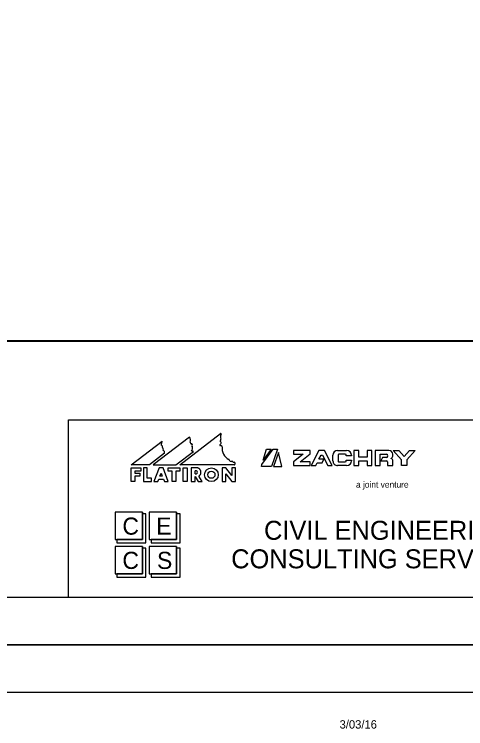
# Model space of a CAD drawing. Extents: x -2251 to 10196, y -13470 to 1199.
# Drawn here: x 1285.2 to 1522.9, y -13469.8 to -13093.7 of the extents above; entities that cross this region are included whole.
import ezdxf

# ---------------------------------------------------------------- set-up
doc = ezdxf.new("R2010")
doc.units = 0
for name, color, linetype in [('Level 3', 7, 'Continuous'), ('RD_SHT_Bndy', 7, 'Continuous'), ('RD_SHT_Iplotshp', 7, 'Continuous'), ('RD_SHT_Logo', 7, 'Continuous'), ('RD_SHT_Misc1', 7, 'Continuous'), ('RD_SHT_Snap', 7, 'Continuous'), ('RD_SHT_TX', 7, 'Continuous'), ('RD_TX_RoadID', 7, 'Continuous')]:
    doc.layers.add(name, color=color, linetype=linetype)

msp = doc.modelspace()

# ---------------------------------------------------------------- linework, layer by layer
at = {"layer": 'Level 3'}
msp.add_line((1465.07, -13363.99), (1465.07, -13363.99), dxfattribs=at)
msp.add_line((1465.07, -13363.99), (1465.07, -13363.99), dxfattribs=at)
msp.add_line((1465.07, -13363.99), (1465.07, -13363.99), dxfattribs=at)
msp.add_line((1465.07, -13363.99), (1465.07, -13363.99), dxfattribs=at)
at = {"layer": 'RD_SHT_Bndy'}
for p, q in [((103.1, -13400.65), (1778.1, -13400.65)), ((1791.65, -13425.65), (31.65, -13425.65)), ((1791.6, -13450.7), (31.6, -13450.65))]:
    msp.add_line(p, q, dxfattribs=at)
msp.add_lwpolyline([(153.4, -12401.26), (1731.08, -12401.26), (1731.08, -13265.57), (153.4, -13265.57)], close=True, dxfattribs=at)
at = {"layer": 'RD_SHT_Iplotshp'}
msp.add_lwpolyline([(-3.35, -12325.65), (1796.65, -12325.65), (1796.65, -13425.65), (-3.35, -13425.65)], close=True, dxfattribs=at)
at = {"layer": 'RD_SHT_Logo'}
for p, q in [((1377.35, -13316.27), (1358.31, -13330.86)), ((1372.32, -13330.86), (1393.74, -13314.44)), ((1346.7, -13330.86), (1362.98, -13318.38)), ((1370.3, -13330.86), (1379.48, -13323.82)), ((1415.56, -13330.77), (1421.47, -13322.59)), ((1420.48, -13322.59), (1416.24, -13328.47)), ((1416.24, -13328.47), (1417.96, -13322.59)), ((1417.96, -13322.59), (1420.48, -13322.59)), ((1423.82, -13322.59), (1420.68, -13331.76)), ((1421.47, -13322.59), (1423.82, -13322.59)), ((1440.93, -13323.35), (1432.22, -13323.35)), ((1432.22, -13323.35), (1432.22, -13325.3)), ((1440.93, -13325.16), (1440.93, -13323.35)), ((1445.58, -13323.35), (1441.53, -13331.3)), ((1448.58, -13323.35), (1445.58, -13323.35)), ((1452.63, -13331.3), (1448.58, -13323.35)), ((1455.44, -13323.35), (1460.18, -13323.35)), ((1466.62, -13323.35), (1464.02, -13323.35)), ((1464.02, -13323.35), (1464.02, -13331.3)), ((1466.62, -13326.8), (1466.62, -13323.35)), ((1470.9, -13323.35), (1470.9, -13326.8)), ((1473.51, -13323.35), (1470.9, -13323.35)), ((1473.5, -13331.3), (1473.51, -13323.35)), ((1482.43, -13323.35), (1475.13, -13323.35)), ((1475.13, -13323.35), (1475.13, -13331.3)), ((1484.68, -13323.35), (1487.64, -13323.35)), ((1489.08, -13328.24), (1484.68, -13323.35)), ((1487.64, -13323.35), (1490.48, -13326.51)), ((1490.48, -13326.51), (1493.32, -13323.35)), ((1496.28, -13323.35), (1491.88, -13328.24)), ((1493.32, -13323.35), (1496.28, -13323.35)), ((1364.27, -13324.74), (1356.29, -13330.86)), ((1424.24, -13324.44), (1421.74, -13331.76)), ((1425.99, -13331.76), (1424.24, -13324.44)), ((1437.2, -13325.3), (1432.22, -13329.24)), ((1432.22, -13325.3), (1437.2, -13325.3)), ((1435.63, -13329.35), (1440.93, -13325.16)), ((1445.57, -13327.99), (1446.71, -13325.75)), ((1446.71, -13325.75), (1447.44, -13325.75)), ((1447.44, -13325.75), (1450.27, -13331.3)), ((1452.94, -13328.8), (1452.94, -13325.85)), ((1455.64, -13325.8), (1455.64, -13328.85)), ((1459.48, -13325.3), (1456.14, -13325.3)), ((1459.98, -13326.15), (1459.98, -13325.8)), ((1462.68, -13326.15), (1459.98, -13326.15)), ((1462.68, -13325.85), (1462.68, -13326.15)), ((1470.9, -13326.8), (1466.62, -13326.8)), ((1477.83, -13331.3), (1477.83, -13325.31)), ((1477.83, -13325.31), (1481.07, -13325.31)), ((1479.03, -13326.97), (1478.11, -13328.77)), ((1481.07, -13326.97), (1479.03, -13326.97)), ((1483.68, -13327.6), (1483.68, -13327.47)), ((1484.43, -13326.36), (1484.43, -13325.35)), ((1356.29, -13330.86), (1346.7, -13330.86)), ((1358.31, -13330.86), (1370.3, -13330.86)), ((1401.19, -13330.86), (1372.32, -13330.86)), ((1415.27, -13331.76), (1415.56, -13330.77)), ((1432.22, -13329.24), (1432.22, -13331.3)), ((1432.22, -13331.3), (1440.93, -13331.3)), ((1440.93, -13329.35), (1435.63, -13329.35)), ((1440.93, -13331.3), (1440.93, -13329.35)), ((1441.53, -13331.3), (1443.88, -13331.3)), ((1443.88, -13331.3), (1444.65, -13329.79)), ((1444.65, -13329.79), (1447.23, -13329.79)), ((1448.15, -13327.99), (1445.57, -13327.99)), ((1447.23, -13329.79), (1448.15, -13327.99)), ((1450.27, -13331.3), (1452.63, -13331.3)), ((1460.18, -13331.3), (1455.44, -13331.3)), ((1456.14, -13329.35), (1459.48, -13329.35)), ((1459.98, -13328.5), (1462.68, -13328.5)), ((1459.98, -13328.85), (1459.98, -13328.5)), ((1462.68, -13328.5), (1462.68, -13328.8)), ((1464.02, -13331.3), (1466.62, -13331.3)), ((1466.62, -13331.3), (1466.62, -13328.8)), ((1466.62, -13328.8), (1470.9, -13328.8)), ((1470.9, -13328.8), (1470.9, -13331.3)), ((1470.9, -13331.3), (1473.5, -13331.3)), ((1475.13, -13331.3), (1477.83, -13331.3)), ((1478.11, -13328.77), (1481.24, -13328.77)), ((1481.74, -13329.27), (1481.74, -13331.3)), ((1481.74, -13331.3), (1484.54, -13331.3)), ((1484.54, -13331.3), (1484.54, -13328.76)), ((1489.08, -13331.3), (1489.08, -13328.24)), ((1491.88, -13331.3), (1489.08, -13331.3)), ((1491.88, -13328.24), (1491.88, -13331.3)), ((1346.72, -13339.7), (1346.72, -13332.5)), ((1346.72, -13332.5), (1351.82, -13332.5)), ((1351.82, -13334.15), (1348.67, -13334.15)), ((1348.67, -13334.15), (1348.67, -13335.21)), ((1348.67, -13335.21), (1351.22, -13335.21)), ((1351.22, -13335.21), (1351.22, -13336.86)), ((1351.82, -13332.5), (1351.82, -13334.15)), ((1355.12, -13332.5), (1353.17, -13332.5)), ((1353.17, -13332.5), (1353.17, -13339.7)), ((1355.12, -13337.9), (1355.12, -13332.5)), ((1361.42, -13332.5), (1358.65, -13339.71)), ((1363.52, -13332.5), (1361.42, -13332.5)), ((1361.83, -13336.86), (1362.47, -13335.2)), ((1362.47, -13335.2), (1363.1, -13336.86)), ((1366.28, -13339.71), (1363.52, -13332.5)), ((1366.22, -13334.15), (1366.22, -13332.5)), ((1366.22, -13332.5), (1372.37, -13332.5)), ((1368.32, -13334.15), (1366.22, -13334.15)), ((1368.32, -13339.71), (1368.32, -13334.15)), ((1372.37, -13334.15), (1370.27, -13334.15)), ((1370.27, -13334.15), (1370.27, -13339.71)), ((1372.37, -13332.5), (1372.37, -13334.15)), ((1374.17, -13339.71), (1374.17, -13332.5)), ((1374.17, -13332.5), (1376.12, -13332.5)), ((1376.12, -13332.5), (1376.12, -13339.71)), ((1381.8, -13332.5), (1378.38, -13332.5)), ((1378.38, -13332.5), (1378.38, -13339.71)), ((1380.33, -13335.66), (1380.33, -13334.01)), ((1396.52, -13332.5), (1394.57, -13332.5)), ((1394.57, -13332.5), (1394.57, -13339.71)), ((1399.67, -13336.53), (1396.52, -13332.5)), ((1401.62, -13332.5), (1399.67, -13332.5)), ((1399.67, -13332.5), (1399.67, -13336.53)), ((1401.62, -13339.71), (1401.62, -13332.5)), ((1420.68, -13331.76), (1415.27, -13331.76)), ((1421.74, -13331.76), (1425.99, -13331.76)), ((1351.22, -13336.86), (1348.67, -13336.86)), ((1348.67, -13336.86), (1348.67, -13339.7)), ((1357.37, -13337.9), (1355.12, -13337.9)), ((1357.37, -13339.71), (1357.37, -13337.9)), ((1360.74, -13339.71), (1361.2, -13338.51)), ((1361.2, -13338.51), (1363.74, -13338.51)), ((1363.1, -13336.86), (1361.83, -13336.86)), ((1363.74, -13338.51), (1364.2, -13339.71)), ((1380.33, -13339.71), (1380.33, -13337.02)), ((1380.33, -13337.02), (1381.94, -13339.71)), ((1384.16, -13339.71), (1382.43, -13336.82)), ((1396.52, -13339.71), (1396.52, -13335.67)), ((1396.52, -13335.67), (1399.67, -13339.71)), ((1348.67, -13339.7), (1346.72, -13339.7)), ((1353.17, -13339.7), (1357.37, -13339.71)), ((1358.65, -13339.71), (1360.74, -13339.71)), ((1364.2, -13339.71), (1366.28, -13339.71)), ((1370.27, -13339.71), (1368.32, -13339.71)), ((1376.12, -13339.71), (1374.17, -13339.71)), ((1378.38, -13339.71), (1380.33, -13339.71)), ((1381.94, -13339.71), (1384.16, -13339.71)), ((1394.57, -13339.71), (1396.52, -13339.71)), ((1399.67, -13339.71), (1401.62, -13339.71)), ((1352.67, -13355.79), (1338.28, -13355.79)), ((1338.28, -13355.79), (1338.28, -13370.23)), ((1352.67, -13370.23), (1352.67, -13355.79)), ((1352.67, -13355.79), (1352.67, -13370.23)), ((1354.48, -13356.7), (1352.67, -13356.7)), ((1354.48, -13372.03), (1354.48, -13356.7)), ((1370.67, -13355.79), (1356.27, -13355.79)), ((1356.27, -13355.79), (1356.27, -13370.23)), ((1370.67, -13370.23), (1370.67, -13355.79)), ((1370.67, -13355.79), (1370.67, -13370.23)), ((1372.48, -13356.7), (1370.67, -13356.7)), ((1372.48, -13372.03), (1372.48, -13356.7)), ((1338.28, -13370.23), (1352.67, -13370.23)), ((1352.67, -13370.23), (1339.17, -13370.23)), ((1339.17, -13370.23), (1339.17, -13372.03)), ((1339.17, -13372.03), (1354.48, -13372.03)), ((1356.27, -13370.23), (1370.67, -13370.23)), ((1370.67, -13370.23), (1357.18, -13370.23)), ((1357.18, -13370.23), (1357.18, -13372.03)), ((1357.18, -13372.03), (1372.48, -13372.03)), ((1352.67, -13373.84), (1338.28, -13373.84)), ((1338.28, -13373.84), (1338.28, -13388.27)), ((1352.67, -13388.27), (1352.67, -13373.84)), ((1352.67, -13373.84), (1352.67, -13388.27)), ((1354.48, -13374.74), (1352.67, -13374.74)), ((1354.48, -13390.07), (1354.48, -13374.74)), ((1370.67, -13373.84), (1356.27, -13373.84)), ((1356.27, -13373.84), (1356.27, -13388.27)), ((1370.67, -13388.27), (1370.67, -13373.84)), ((1370.67, -13373.84), (1370.67, -13388.27)), ((1372.48, -13374.74), (1370.67, -13374.74)), ((1372.48, -13390.07), (1372.48, -13374.74)), ((1338.28, -13388.27), (1352.67, -13388.27)), ((1352.67, -13388.27), (1339.17, -13388.27)), ((1339.17, -13388.27), (1339.17, -13390.07)), ((1339.17, -13390.07), (1354.48, -13390.07)), ((1356.27, -13388.27), (1370.67, -13388.27)), ((1370.67, -13388.27), (1357.18, -13388.27)), ((1357.18, -13388.27), (1357.18, -13390.07)), ((1357.18, -13390.07), (1372.48, -13390.07))]:
    msp.add_line(p, q, dxfattribs=at)
for radius in [3.6, 1.9]:
    msp.add_circle((1388.95, -13336.1), radius, dxfattribs=at)
for centre, radius, start, end in [((1375.05, -13318.02), 2.89, 342.0343, 37.2653), ((1397.87, -13316.34), 4.17, 156.4699, 195.3053), ((1393.86, -13314.6), 0.2, 336.4699, 127.4657), ((1366.29, -13320.12), 3.74, 152.2252, 185.8662), ((1377.99, -13318.97), 0.2, 162.0343, 220.8638), ((1376.86, -13319.95), 1.3, 11.8745, 40.8638), ((1378.32, -13319.64), 0.2, 191.8745, 279.8173), ((1378.44, -13320.33), 0.499, 44.4799, 99.8173), ((1379.5, -13320.72), 0.843, 144.641, 212.5499), ((1378.65, -13320.12), 0.2, 324.641, 44.4799), ((1393.57, -13320.5), 0.2, 133.0036, 262.3069), ((1391.59, -13318.37), 2.7, 313.0036, 343.6807), ((1393.73, -13318.39), 0.2, 129.4079, 246.863), ((1393.13, -13317.66), 0.749, 309.4079, 17.0499), ((1393.27, -13319.47), 0.973, 20.4113, 66.863), ((1362.1, -13321.62), 1.21, 351.6466, 67.1294), ((1364.29, -13321.94), 1, 171.6466, 221.9371), ((1363.11, -13323.01), 0.592, 327.6019, 41.9371), ((1363.3, -13324.33), 1.05, 337.4201, 73.1261), ((1375.8, -13322.18), 3.16, 331.2486, 18.4584), ((1378.92, -13324.44), 0.827, 48.0701, 115.7229), ((1393.31, -13322.44), 1.76, 45.283, 82.3069), ((1394.4, -13321.33), 0.2, 353.8329, 45.283), ((1401.36, -13322.08), 6.8, 173.8329, 242.3928), ((1455.44, -13325.85), 2.5, 89.9984, 179.9984), ((1460.18, -13325.85), 2.5, 359.9984, 89.9984), ((1482.43, -13325.35), 2, 359.9984, 89.9984), ((1456.14, -13325.8), 0.5, 89.9984, 179.9984), ((1459.48, -13325.8), 0.5, 359.9984, 89.9984), ((1481.07, -13326.14), 0.831, 269.9984, 89.9984), ((1483.23, -13326.36), 1.2, 291.95, 359.9984), ((1483.34, -13328.76), 1.2, 359.9984, 73.7977), ((1398.12, -13328.28), 0.2, 9.0833, 62.3928), ((1399.35, -13328.09), 1.04, 189.0833, 295.769), ((1399.89, -13329.21), 0.2, 33.7112, 115.769), ((1400.89, -13328.54), 1.01, 213.7112, 268.6299), ((1400.86, -13329.74), 0.2, 78.9712, 88.6299), ((1400.75, -13330.3), 0.767, 320.912, 78.9712), ((1401.19, -13330.66), 0.2, 269.9984, 320.912), ((1455.44, -13328.8), 2.5, 179.9984, 269.9984), ((1456.14, -13328.85), 0.5, 179.9984, 269.9984), ((1459.48, -13328.85), 0.5, 269.9984, 359.9984), ((1460.18, -13328.8), 2.5, 269.9984, 359.9984), ((1481.24, -13329.27), 0.5, 359.9984, 89.9984)]:
    msp.add_arc(centre, radius, start, end, dxfattribs=at)
msp.add_ellipse((1380.33, -13334.83), major_axis=(1.36, 0), ratio=0.609965, start_param=4.712389, end_param=7.853982, dxfattribs=at)
msp.add_open_spline([(1382.43, -13336.82), (1382.51, -13336.76), (1382.59, -13336.7), (1382.81, -13336.49), (1382.95, -13336.34), (1383.13, -13336.07), (1383.19, -13335.97), (1383.29, -13335.77), (1383.34, -13335.66), (1383.41, -13335.44), (1383.44, -13335.32), (1383.47, -13335.08), (1383.48, -13334.96), (1383.48, -13334.71), (1383.47, -13334.59), (1383.44, -13334.35), (1383.41, -13334.23), (1383.34, -13334.01), (1383.29, -13333.9), (1383.19, -13333.7), (1383.13, -13333.6), (1382.95, -13333.33), (1382.81, -13333.18), (1382.52, -13332.91), (1382.37, -13332.8), (1382.08, -13332.63), (1381.94, -13332.56), (1381.8, -13332.5)], degree=3, dxfattribs=at)
at = {"layer": 'RD_SHT_Misc1'}
msp.add_lwpolyline([(1796.65, -13425.65), (1796.68, -12325.65), (96.68, -12325.6), (96.65, -13425.6)], close=True, dxfattribs=at)
at = {"layer": 'RD_SHT_Snap'}
msp.add_lwpolyline([(8.15, -12325.65), (1808.15, -12325.65), (1808.15, -13425.65), (8.15, -13425.65)], close=True, dxfattribs=at)
at = {"layer": 'RD_SHT_TX'}
for p, q in [((1313.76, -13400.65), (1313.76, -13307.15)), ((1313.76, -13400.65), (1313.76, -13307.15)), ((1313.76, -13307.15), (1778.1, -13307.15))]:
    msp.add_line(p, q, dxfattribs=at)
at = {"layer": 'RD_TX_RoadID'}
msp.add_lwpolyline([(150.54, -13265.73), (1733.93, -13265.73), (1733.93, -12462.61), (150.54, -12462.61)], close=True, dxfattribs=at)

# ---------------------------------------------------------------- texts
at = {"layer": 'RD_SHT_Logo'}
msp.add_text('a joint venture', height=3.3, rotation=359.9984, dxfattribs=at).set_placement((1465.08, -13342.93))
for s, height, p in [('C', 9.02, (1342.11, -13367.66)), ('E', 9.02, (1359.9, -13367.66)), ('CIVIL ENGINEERING', 10, (1416.67, -13370.38)), ('C', 9.02, (1342.11, -13385.71)), ('S', 9.02, (1360.32, -13385.71)), ('CONSULTING SERVICES, INC.', 10, (1399.39, -13385.38))]:
    msp.add_text(s, height=height, dxfattribs=at).set_placement(p)
at = {"layer": 'RD_SHT_TX'}
msp.add_text('3/03/16', height=4.408, dxfattribs=at).set_placement((1456.45, -13469.78))

doc.saveas('drawing.dxf')
